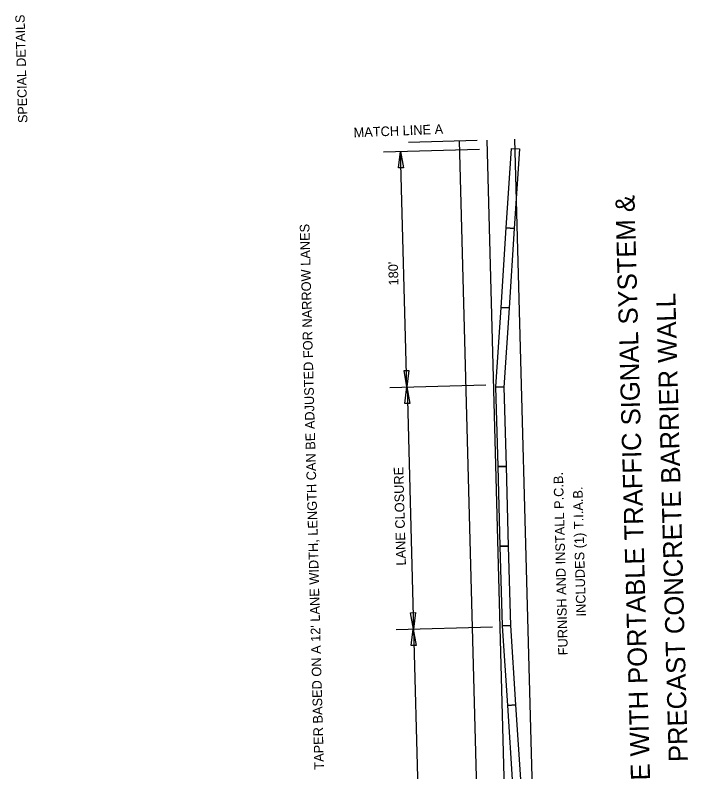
# Model space of a CAD drawing. Extents: x 1926836 to 1933254, y 596317 to 604524.
# Drawn here: x 1930711.6 to 1931133.5, y 597267.9 to 597742.7 of the extents above; entities that cross this region are included whole.
import ezdxf

# ---------------------------------------------------------------- set-up
doc = ezdxf.new("R2010")
doc.units = 0
for name, color, linetype in [('Default', 7, 'Continuous'), ('R_Border', 7, 'Continuous'), ('R_No Plot', 7, 'Continuous'), ('T_Vehicle Path Rt', 7, 'Continuous')]:
    doc.layers.add(name, color=color, linetype=linetype)

msp = doc.modelspace()

# ---------------------------------------------------------------- linework, layer by layer
at = {"layer": 'Default'}
for p, q in [((1930958.38, 597663.01), (1931001.42, 597664.17)), ((1931008.05, 597000.74), (1930990.25, 597663.87)), ((1931025.43, 597001.21), (1931007.63, 597664.33)), ((1931042.81, 597001.68), (1931025.01, 597664.8)), ((1930942.56, 597656.95), (1931002.89, 597658.57)), ((1930952.07, 597646.9), (1930953.34, 597657.24)), ((1930957.31, 597509.4), (1930953.34, 597657.24)), ((1930953.34, 597657.24), (1930955.16, 597646.98)), ((1930955.16, 597646.98), (1930952.07, 597646.9)), ((1930955.49, 597519.66), (1930958.58, 597519.74)), ((1930957.31, 597509.4), (1930955.49, 597519.66)), ((1930958.58, 597519.74), (1930957.31, 597509.4)), ((1930946.53, 597509.11), (1931006.85, 597510.73)), ((1930956.04, 597499.06), (1930957.31, 597509.4)), ((1930957.31, 597509.4), (1930959.13, 597499.14)), ((1930957.44, 597509.4), (1930961.39, 597357.52)), ((1930959.13, 597499.14), (1930956.04, 597499.06)), ((1930959.56, 597367.77), (1930962.66, 597367.86)), ((1930961.39, 597357.52), (1930959.56, 597367.77)), ((1930962.66, 597367.86), (1930961.39, 597357.52)), ((1930950.6, 597357.23), (1931010.93, 597358.85)), ((1930959.98, 597347.17), (1930961.25, 597357.51)), ((1930961.25, 597357.51), (1930963.07, 597347.25)), ((1930961.39, 597357.52), (1930968.09, 597107.88)), ((1930963.07, 597347.25), (1930959.98, 597347.17))]:
    msp.add_line(p, q, dxfattribs=at)
at = {"layer": 'T_Vehicle Path Rt'}
for points in [[(1931019.61, 597609.21), (1931022.83, 597659.1), (1931027.82, 597658.78), (1931024.6, 597608.89)], [(1931016.38, 597559.31), (1931019.61, 597609.21), (1931024.6, 597608.89), (1931021.37, 597558.99)], [(1931013.16, 597509.42), (1931016.38, 597559.31), (1931021.37, 597558.99), (1931018.15, 597509.09)], [(1931014.5, 597459.43), (1931013.16, 597509.42), (1931018.16, 597509.55), (1931019.5, 597459.57)], [(1931015.84, 597409.45), (1931014.5, 597459.43), (1931019.5, 597459.57), (1931020.84, 597409.59)], [(1931017.18, 597359.47), (1931015.84, 597409.45), (1931020.84, 597409.59), (1931022.18, 597359.6)], [(1931020.5, 597309.58), (1931017.18, 597359.47), (1931022.17, 597359.8), (1931025.49, 597309.91)], [(1931023.81, 597259.69), (1931020.5, 597309.58), (1931025.49, 597309.91), (1931028.8, 597260.02)]]:
    msp.add_lwpolyline(points, close=True, dxfattribs=at)

# ---------------------------------------------------------------- texts
at = {"layer": 'Default'}
for s, height, rotation, p in [('MATCH LINE A', 6, 2.3436, (1930924, 597666.01)), ('LANE CLOSURE WITH PORTABLE TRAFFIC SIGNAL SYSTEM &', 12, 91.5377, (1931112.86, 597149.5)), ("180'", 6, 91.5377, (1930951.98, 597573.19)), ('PRECAST CONCRETE BARRIER WALL', 12, 91.5377, (1931133.52, 597274.3)), ('LANE CLOSURE', 6, 91.5377, (1930956.7, 597397.42)), ('FURNISH AND INSTALL P.C.B. ', 6, 91.5377, (1931058.23, 597341.15)), ('INCLUDES (1) T.I.A.B.', 6, 91.5377, (1931069.58, 597365.47))]:
    msp.add_text(s, height=height, rotation=rotation, dxfattribs=at).set_placement(p)
at = {"layer": 'R_Border'}
msp.add_text('SPECIAL DETAILS', height=5.862, rotation=91.5377, dxfattribs=at).set_placement((1930719.38, 597675.16))
at = {"layer": 'R_No Plot'}
msp.add_text("TAPER BASED ON A 12' LANE WIDTH, LENGTH CAN BE ADJUSTED FOR NARROW LANES", height=6, rotation=91.5377, dxfattribs=at).set_placement((1930905.3, 597269.35))

doc.saveas('drawing.dxf')
